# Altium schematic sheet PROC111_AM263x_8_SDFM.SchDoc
size 431 x 279 mm; Date: Not shown in title block; ApprovedBy: Not shown in title block; CheckedBy: Not shown in title block; Author: Not shown in title block; CompanyName: Not shown in title block; Engineer: Not shown in title block; Organization: Not shown in title block; Address1: Not shown in title block; Address2: Not shown in title block; Address3: Not shown in title block; Address4: Not shown in title block; DocumentNumber: 12; Revision: Use project parameter SCH_Rev; SheetNumber: 12; SheetTotal: 24; PageSetup: Record=PageOptions¦CenterHorizontal=True¦CenterVertical=True¦PrintScale=1.00¦XCorrection=1.00¦YCorrection=1.00¦PrintKind=0¦BorderSize=5000000¦LeftOffset=0¦BottomOffset=0¦Orientation=2¦PaperLength=1000¦PaperWidth=1000¦Scale=100¦PaperSource=15¦PrintQuality=600¦MediaType=1¦DitherType=10¦PaperKind=Letter¦PrintScaleMode=1
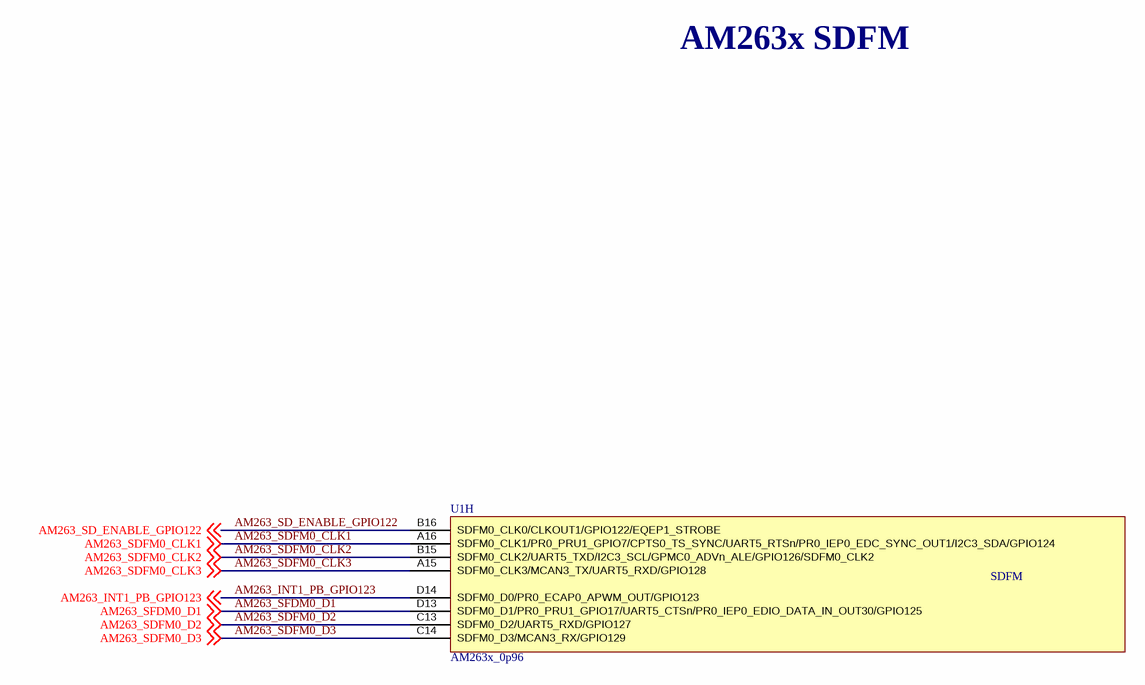
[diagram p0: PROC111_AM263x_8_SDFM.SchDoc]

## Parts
U1  AM263x_0p96  [ZCZ (S-PBGA-N324)]  (part H of 13)

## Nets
AM263_INT1_PB_GPIO123: U1.D14(SDFM0_D0/PR0_ECAP0_APWM_OUT/GPIO123) ; off-sheet AM263_INT1_PB_GPIO123
AM263_SD_ENABLE_GPIO122: U1.B16(SDFM0_CLK0/CLKOUT1/GPIO122/EQEP1_STROBE) ; off-sheet AM263_SD_ENABLE_GPIO122
AM263_SDFM0_CLK1: U1.A16(SDFM0_CLK1/PR0_PRU1_GPIO7/CPTS0_TS_SYNC/UART5_RTSn/PR0_IEP0_EDC_SYNC_OUT1/I2C3_SDA/GPIO124) ; off-sheet AM263_SDFM0_CLK1
AM263_SDFM0_CLK2: U1.B15(SDFM0_CLK2/UART5_TXD/I2C3_SCL/GPMC0_ADVn_ALE/GPIO126/SDFM0_CLK2) ; off-sheet AM263_SDFM0_CLK2
AM263_SDFM0_CLK3: U1.A15(SDFM0_CLK3/MCAN3_TX/UART5_RXD/GPIO128) ; off-sheet AM263_SDFM0_CLK3
AM263_SDFM0_D2: U1.C13(SDFM0_D2/UART5_RXD/GPIO127) ; off-sheet AM263_SDFM0_D2
AM263_SDFM0_D3: U1.C14(SDFM0_D3/MCAN3_RX/GPIO129) ; off-sheet AM263_SDFM0_D3
AM263_SFDM0_D1: U1.D13(SDFM0_D1/PR0_PRU1_GPIO17/UART5_CTSn/PR0_IEP0_EDIO_DATA_IN_OUT30/GPIO125) ; off-sheet AM263_SFDM0_D1

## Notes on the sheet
- AM263x SDFM

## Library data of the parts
U1 = AM263x_0p96: Sitara AM263x MCU (Pinlist Revision 0.96, Pinmux 0.98)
